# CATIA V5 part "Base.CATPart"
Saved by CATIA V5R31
Part number: Part1
Bounding box of the stored display mesh (mm): x -50 to 50, y -25 to 25, z 0 to 50
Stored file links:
  D:\PROJECTS\Project 2021\US EDITION\CATIA V5 6R 2021\Resources\Part Files\c12_catia_v5_6r2021_prt\c12_catia_v5-6r2021 figr_12-22\Base.CATPart
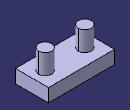
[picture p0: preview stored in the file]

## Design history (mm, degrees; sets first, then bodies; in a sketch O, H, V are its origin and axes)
Body1 (main body)
  Sketch1 on xy-plane, origin (0, 0, 0), H (1, 0, 0), V (0, 1, 0)
    line L1 (50, 25) -> (50, -25)
    line L2 (50, -25) -> (-50, -25)
    line L3 (-50, -25) -> (-50, 25)
    line L4 (-50, 25) -> (50, 25)
    circle A1 centre (-30, 0) radius 10
    point P5 (-30, 0)
    circle A2 centre (30, 0) radius 10
    length L2 = 100
    length L1 = 50
    radius A1 = 10
    distance P5 V = 30
    vertical: L1 V, L3 V
    horizontal: L2 H, L4 H
    equidistance: L1 L3 O, L2 L4 O
    coincidence: P5 H
    symmetry: A1 A2 V
  MultiPad1: profile Sketch1, domains (length 20; length 50; length 50)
